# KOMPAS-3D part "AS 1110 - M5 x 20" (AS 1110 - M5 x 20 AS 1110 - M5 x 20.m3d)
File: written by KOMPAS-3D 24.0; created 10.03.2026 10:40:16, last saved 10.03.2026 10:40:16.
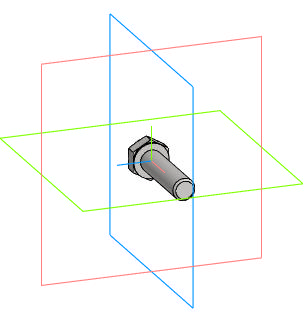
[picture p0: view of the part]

Document properties: Автор: R2D2; Полное имя файла: C:\Users\R2D2\Downloads\AS 1110 - M5 x 20 AS 1110 - M5 x 20.m3d

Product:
- Body: Solid1  | qty 1
- Part/product: AS 1110 - M5 x 20
    Комментарий: Болты и винты   шестигранные точные   метрические ISO
    additional columns: Сталь, мягкая

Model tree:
1. Solid1  (labels: Solid1)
